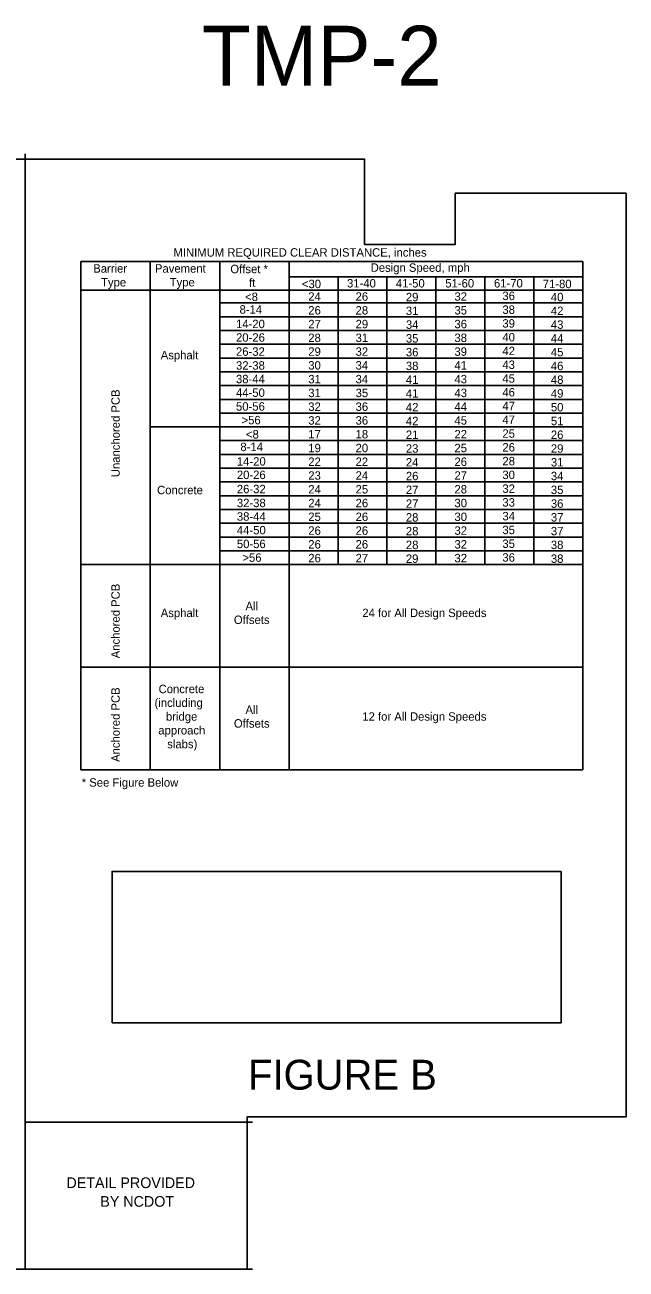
# Model space of a CAD drawing. Extents: x 2487012 to 2497594, y 369516 to 371986.
# Drawn here: x 2487943 to 2488507, y 370218 to 371384 of the extents above; entities that cross this region are included whole.
import ezdxf

# ---------------------------------------------------------------- set-up
doc = ezdxf.new("R2010")
doc.units = 0
for name, color, linetype in [('TC SHEET BORDER LINE THIN', 7, 'Continuous'), ('TC SHEET LAYOUT SHAPE', 7, 'Continuous'), ('TC SHEET TEXT', 7, 'Continuous'), ('Text', 7, 'Continuous')]:
    doc.layers.add(name, color=color, linetype=linetype)

msp = doc.modelspace()

# ---------------------------------------------------------------- linework, layer by layer
at = {"layer": 'TC SHEET BORDER LINE THIN'}
for p, q in [((2487943.6, 371263.3), (2487943.6, 370218.3)), ((2487995.8, 371162.3), (2488466.1, 371162.3)), ((2487995.8, 371162.3), (2487995.8, 370686.1)), ((2488060.8, 371162.3), (2488060.8, 370686.1)), ((2488060.8, 371162.3), (2488060.8, 370686.1)), ((2488060.8, 371162.3), (2488060.8, 370686.1)), ((2488125.9, 371162.3), (2488125.9, 370686.1)), ((2488125.9, 371162.3), (2488125.9, 370686.1)), ((2488190.9, 371162.3), (2488190.9, 370686.1)), ((2488466.1, 371162.3), (2488466.1, 370686.1)), ((2488190.9, 371147.9), (2488466.1, 371147.9)), ((2488236.8, 371147.9), (2488236.8, 370878.4)), ((2488282.6, 371147.9), (2488282.6, 370878.4)), ((2488328.5, 371147.9), (2488328.5, 370878.4)), ((2488374.4, 371147.9), (2488374.4, 370878.4)), ((2488420.2, 371147.9), (2488420.2, 370878.4)), ((2487995.8, 371135.6), (2488466.1, 371135.6)), ((2488236.8, 371135.6), (2488236.8, 370878.4)), ((2488466.1, 371135.6), (2488466.1, 370878.4)), ((2488125.9, 371123.5), (2488466.1, 371123.5)), ((2488125.9, 371110.6), (2488466.1, 371110.6)), ((2488125.9, 371097.7), (2488466.1, 371097.7)), ((2488125.9, 371084.8), (2488466.1, 371084.8)), ((2488125.9, 371071.9), (2488466.1, 371071.9)), ((2488125.9, 371059), (2488466.1, 371059)), ((2488125.9, 371046.1), (2488466.1, 371046.1)), ((2488125.9, 371033.2), (2488466.1, 371033.2)), ((2488125.9, 371020.3), (2488466.1, 371020.3)), ((2488060.8, 371007.4), (2488466.1, 371007.4)), ((2488125.9, 370994.5), (2488466.1, 370994.5)), ((2488125.9, 370981.6), (2488466.1, 370981.6)), ((2488125.9, 370968.7), (2488466.1, 370968.7)), ((2488125.9, 370955.8), (2488466.1, 370955.8)), ((2488125.9, 370942.9), (2488466.1, 370942.9)), ((2488125.9, 370930), (2488466.1, 370930)), ((2488125.9, 370917.1), (2488466.1, 370917.1)), ((2488125.9, 370904.2), (2488466.1, 370904.2)), ((2488125.9, 370891.3), (2488466.1, 370891.3)), ((2487995.8, 370878.4), (2488466.1, 370878.4)), ((2487995.8, 370782.2), (2488466.1, 370782.2)), ((2487995.8, 370686.1), (2488466.1, 370686.1)), ((2488156.6, 370355.8), (2487943.6, 370355.8)), ((2488156.6, 370218.3), (2487943.6, 370218.3))]:
    msp.add_line(p, q, dxfattribs=at)
at = {"layer": 'TC SHEET LAYOUT SHAPE'}
msp.add_lwpolyline([(2487016.6, 370666.8), (2487016.6, 370976.2), (2487016.6, 371248.3), (2487026.6, 371258.3), (2487469.6, 371258.3), (2487940.6, 371258.3), (2488261.6, 371258.3), (2488261.6, 371178.3), (2488346.6, 371178.3), (2488346.6, 371226.3), (2488506.6, 371226.3), (2488506.6, 370891.3), (2488506.6, 370612.1), (2488506.6, 370360.8), (2488151.6, 370360.8), (2488151.6, 370218.3), (2487778.4, 370218.3), (2487608.9, 370218.3), (2487256.1, 370218.3), (2487016.6, 370218.3)], close=True, dxfattribs=at)
at = {"layer": 'Text'}
msp.add_lwpolyline([(2488025.1, 370449), (2488445.6, 370449), (2488445.6, 370590.9), (2488025.1, 370590.9)], close=True, dxfattribs=at)

# ---------------------------------------------------------------- texts
at = {"layer": 'TC SHEET LAYOUT SHAPE'}
msp.add_text('TMP-2', height=56, rotation=0.0001, dxfattribs=at).set_placement((2488109.2, 371327.2))
at = {"layer": 'TC SHEET TEXT'}
for s, height, p in [('MINIMUM REQUIRED CLEAR DISTANCE, inches', 7.9, (2488082.6, 371166.9)), ('Barrier', 7.9, (2488007.5, 371151.9)), ('Pavement', 7.9, (2488065.3, 371151.9)), ('Offset *', 7.9, (2488135.9, 371151.4)), ('Design Speed, mph', 7.9, (2488267.3, 371152.7)), ('Type', 7.9, (2488014.8, 371139)), ('Type', 7.9, (2488079.1, 371139)), ('ft', 7.9, (2488153.4, 371138.5)), ('<30', 7.9, (2488202.9, 371137.4)), ('31-40', 7.9, (2488245.2, 371138)), ('41-50', 7.9, (2488290.9, 371138)), ('51-60', 7.9, (2488337.2, 371138)), ('61-70', 7.9, (2488382.8, 371138)), ('71-80', 7.9, (2488428.5, 371137.4)), ('<8', 7.9, (2488149.7, 371125.3)), ('24', 7.9, (2488208.9, 371125.6)), ('26', 7.9, (2488253.2, 371125.6)), ('29', 7.9, (2488300.3, 371125.1)), ('32', 7.9, (2488345.8, 371125.6)), ('36', 7.9, (2488390.7, 371126.2)), ('40', 7.9, (2488436.1, 371125.1)), ('8-14', 7.9, (2488144.5, 371113.5)), ('26', 7.9, (2488208.9, 371112.7)), ('28', 7.9, (2488253.2, 371112.7)), ('31', 7.9, (2488300.3, 371112.2)), ('35', 7.9, (2488345.8, 371112.7)), ('38', 7.9, (2488390.7, 371113.3)), ('42', 7.9, (2488436.1, 371112.2)), ('14-20', 7.9, (2488141.2, 371099.9)), ('27', 7.9, (2488208.9, 371099.8)), ('29', 7.9, (2488253.2, 371099.8)), ('34', 7.9, (2488300.3, 371099.3)), ('36', 7.9, (2488345.8, 371099.8)), ('39', 7.9, (2488390.7, 371100.4)), ('43', 7.9, (2488436.1, 371099.3)), ('20-26', 7.9, (2488141.2, 371087.2)), ('28', 7.9, (2488208.9, 371086.9)), ('31', 7.9, (2488253.2, 371086.9)), ('35', 7.9, (2488300.3, 371086.4)), ('38', 7.9, (2488345.8, 371086.9)), ('40', 7.9, (2488390.7, 371087.5)), ('44', 7.9, (2488436.1, 371086.4)), ('26-32', 7.9, (2488141.2, 371074)), ('29', 7.9, (2488208.9, 371074)), ('32', 7.9, (2488253.2, 371074)), ('36', 7.9, (2488300.3, 371073.5)), ('39', 7.9, (2488345.8, 371074)), ('42', 7.9, (2488390.7, 371074.6)), ('Asphalt', 7.9, (2488070.7, 371070.7)), ('45', 7.9, (2488436.1, 371073.5)), ('32-38', 7.9, (2488141.2, 371061)), ('30', 7.9, (2488208.9, 371061.1)), ('34', 7.9, (2488253.2, 371061.1)), ('38', 7.9, (2488300.3, 371060.6)), ('41', 7.9, (2488345.8, 371061.1)), ('43', 7.9, (2488390.7, 371061.7)), ('46', 7.9, (2488436.1, 371060.6)), ('38-44', 7.9, (2488141.2, 371048.3)), ('31', 7.9, (2488208.9, 371048.2)), ('34', 7.9, (2488253.2, 371048.2)), ('41', 7.9, (2488300.3, 371047.7)), ('43', 7.9, (2488345.8, 371048.2)), ('45', 7.9, (2488390.7, 371048.8)), ('48', 7.9, (2488436.1, 371047.7)), ('44-50', 7.9, (2488141.2, 371035.5)), ('31', 7.9, (2488208.9, 371035.3)), ('35', 7.9, (2488253.2, 371035.3)), ('41', 7.9, (2488300.3, 371034.8)), ('43', 7.9, (2488345.8, 371035.3)), ('46', 7.9, (2488390.7, 371035.9)), ('49', 7.9, (2488436.1, 371034.8)), ('50-56', 7.9, (2488141.2, 371022.6)), ('32', 7.9, (2488208.9, 371022.4)), ('36', 7.9, (2488253.2, 371022.4)), ('42', 7.9, (2488300.3, 371021.9)), ('44', 7.9, (2488345.8, 371022.4)), ('47', 7.9, (2488390.7, 371023)), ('50', 7.9, (2488436.1, 371021.9)), ('>56', 7.9, (2488146.4, 371009.8)), ('32', 7.9, (2488208.9, 371009.5)), ('36', 7.9, (2488253.2, 371009.5)), ('42', 7.9, (2488300.3, 371009)), ('45', 7.9, (2488345.8, 371009.5)), ('47', 7.9, (2488390.7, 371010.1)), ('51', 7.9, (2488436.1, 371009)), ('<8', 7.9, (2488150.5, 370996.5)), ('17', 7.9, (2488208.9, 370996.6)), ('18', 7.9, (2488253.2, 370996.6)), ('21', 7.9, (2488300.3, 370996.1)), ('22', 7.9, (2488345.8, 370996.6)), ('25', 7.9, (2488390.7, 370997.2)), ('26', 7.9, (2488436.1, 370996.1)), ('8-14', 7.9, (2488145.3, 370984.7)), ('19', 7.9, (2488208.9, 370983.7)), ('20', 7.9, (2488253.2, 370983.7)), ('23', 7.9, (2488300.3, 370983.2)), ('25', 7.9, (2488345.8, 370983.7)), ('26', 7.9, (2488390.7, 370984.3)), ('29', 7.9, (2488436.1, 370983.2)), ('14-20', 7.9, (2488142, 370971.1)), ('22', 7.9, (2488208.9, 370970.8)), ('22', 7.9, (2488253.2, 370970.8)), ('24', 7.9, (2488300.3, 370970.3)), ('26', 7.9, (2488345.8, 370970.8)), ('28', 7.9, (2488390.7, 370971.4)), ('31', 7.9, (2488436.1, 370970.3)), ('20-26', 7.9, (2488142, 370958.5)), ('23', 7.9, (2488208.9, 370957.9)), ('24', 7.9, (2488253.2, 370957.9)), ('26', 7.9, (2488300.3, 370957.4)), ('27', 7.9, (2488345.8, 370957.9)), ('30', 7.9, (2488390.7, 370958.5)), ('34', 7.9, (2488436.1, 370957.4)), ('32', 7.9, (2488390.7, 370945.6)), ('Concrete', 7.9, (2488067.3, 370944.3)), ('26-32', 7.9, (2488142, 370945.2)), ('24', 7.9, (2488208.9, 370945)), ('25', 7.9, (2488253.2, 370945)), ('27', 7.9, (2488300.3, 370944.5)), ('28', 7.9, (2488345.8, 370945)), ('35', 7.9, (2488436.1, 370944.5)), ('32-38', 7.9, (2488142, 370932.2)), ('24', 7.9, (2488208.9, 370932.1)), ('26', 7.9, (2488253.2, 370932.1)), ('27', 7.9, (2488300.3, 370931.6)), ('30', 7.9, (2488345.8, 370932.1)), ('33', 7.9, (2488390.7, 370932.7)), ('36', 7.9, (2488436.1, 370931.6)), ('38-44', 7.9, (2488142, 370919.5)), ('25', 7.9, (2488208.9, 370919.2)), ('26', 7.9, (2488253.2, 370919.2)), ('28', 7.9, (2488300.3, 370918.7)), ('30', 7.9, (2488345.8, 370919.2)), ('34', 7.9, (2488390.7, 370919.8)), ('37', 7.9, (2488436.1, 370918.7)), ('44-50', 7.9, (2488142, 370906.7)), ('26', 7.9, (2488208.9, 370906.3)), ('26', 7.9, (2488253.2, 370906.3)), ('28', 7.9, (2488300.3, 370905.8)), ('32', 7.9, (2488345.8, 370906.3)), ('35', 7.9, (2488390.7, 370906.9)), ('37', 7.9, (2488436.1, 370905.8)), ('50-56', 7.9, (2488142, 370893.8)), ('26', 7.9, (2488208.9, 370893.4)), ('26', 7.9, (2488253.2, 370893.4)), ('28', 7.9, (2488300.3, 370892.9)), ('32', 7.9, (2488345.8, 370893.4)), ('35', 7.9, (2488390.7, 370894)), ('38', 7.9, (2488436.1, 370892.9)), ('>56', 7.9, (2488147.2, 370881)), ('26', 7.9, (2488208.9, 370880.5)), ('27', 7.9, (2488253.2, 370880.5)), ('29', 7.9, (2488300.3, 370880)), ('32', 7.9, (2488345.8, 370880.5)), ('36', 7.9, (2488390.7, 370881.1)), ('38', 7.9, (2488436.1, 370880)), ('Asphalt', 7.9, (2488070.7, 370829.2)), ('All', 7.9, (2488150.1, 370835.6)), ('24 for All Design Speeds', 7.9, (2488259.5, 370829.2)), ('Offsets', 7.9, (2488139.2, 370822.7)), ('Concrete', 7.9, (2488068.7, 370757.9)), ('(including', 7.9, (2488064.9, 370745)), ('All', 7.9, (2488150.1, 370738.5)), ('bridge', 7.9, (2488075.6, 370732.1)), ('Offsets', 7.9, (2488139.2, 370725.6)), ('12 for All Design Speeds', 7.9, (2488259.5, 370732.1)), ('approach', 7.9, (2488068.4, 370719.2)), ('slabs)', 7.9, (2488076.8, 370706.3)), ('* See Figure Below', 7.9, (2487996.7, 370670.3)), ('FIGURE B', 28, (2488152.5, 370386.4)), ('DETAIL PROVIDED', 10, (2487982.4, 370294.2)), ('BY NCDOT', 10, (2488014.1, 370276.7))]:
    msp.add_text(s, height=height, dxfattribs=at).set_placement(p)
for s, p in [('Unanchored PCB', (2488032.3, 370960.3)), ('Anchored PCB', (2488032.3, 370790.6)), ('Anchored PCB', (2488032.3, 370693.5))]:
    msp.add_text(s, height=7.9, rotation=90, dxfattribs=at).set_placement(p)

doc.saveas('drawing.dxf')
